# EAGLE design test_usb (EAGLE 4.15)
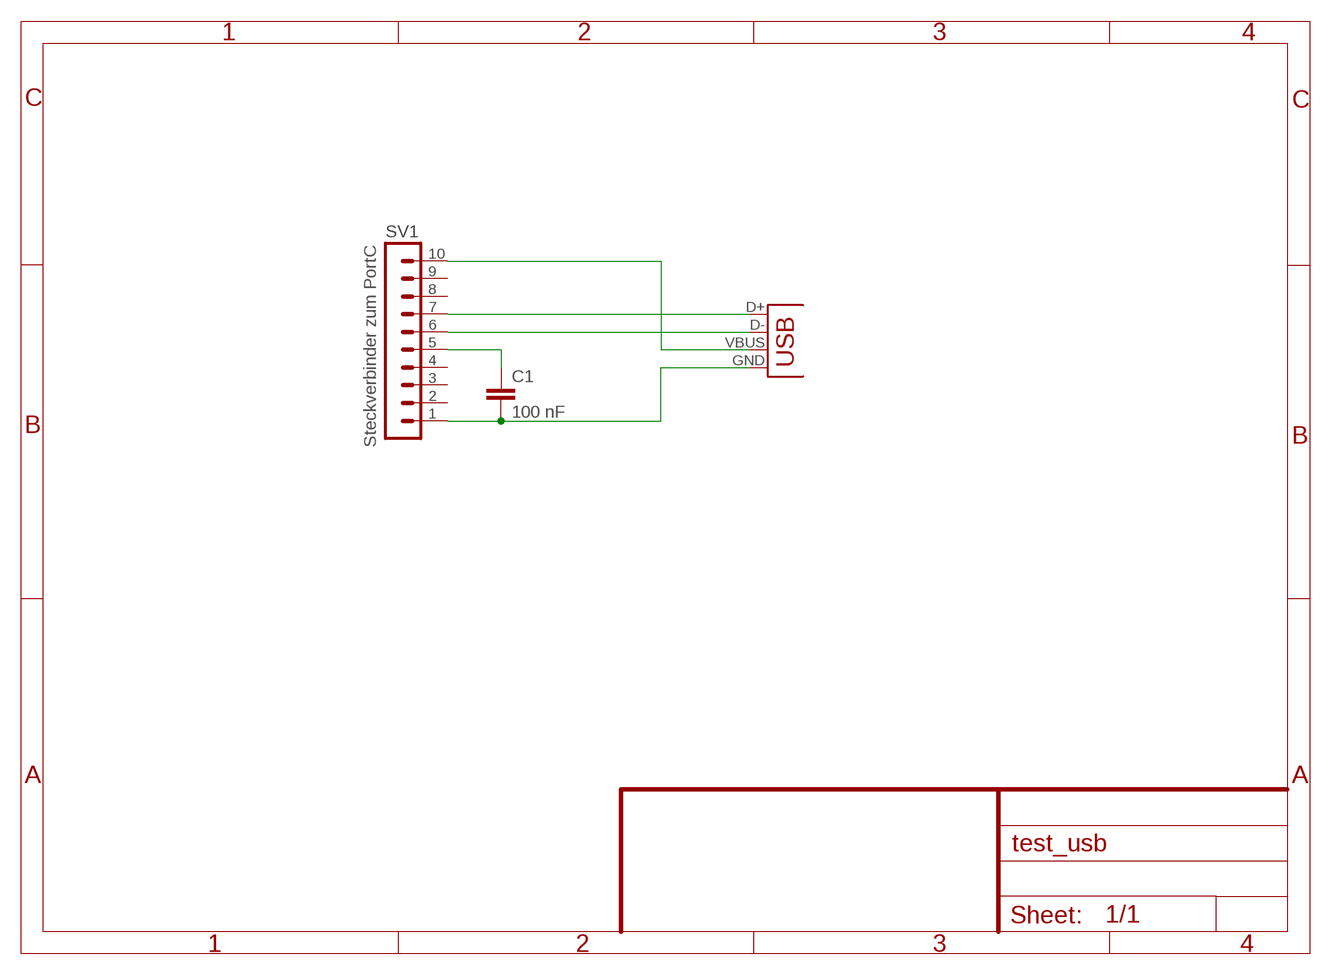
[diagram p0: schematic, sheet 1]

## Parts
C1  100 nF  C-EU025-025X050  [C025-025X050]
SV1  Steckverbinder zum PortC  MA10-1W  [MA10-1W]
X1  USB-B-H  [USB-B-H]

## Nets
N$2: SV1.10 X1.VBUS
N$3: SV1.7 X1.D+
N$4: SV1.6 X1.D-
N$5: C1.1 SV1.5
VSS: C1.2 SV1.1 X1.GND
Unconnected: SV1.2 SV1.3 SV1.4 SV1.8 SV1.9

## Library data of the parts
C1 = rcl:C-EU: CAPACITOR, European symbol
SV1 = con-lstb:MA10-1W: PIN HEADER
X1 = con-usb:USB: USB Connectors

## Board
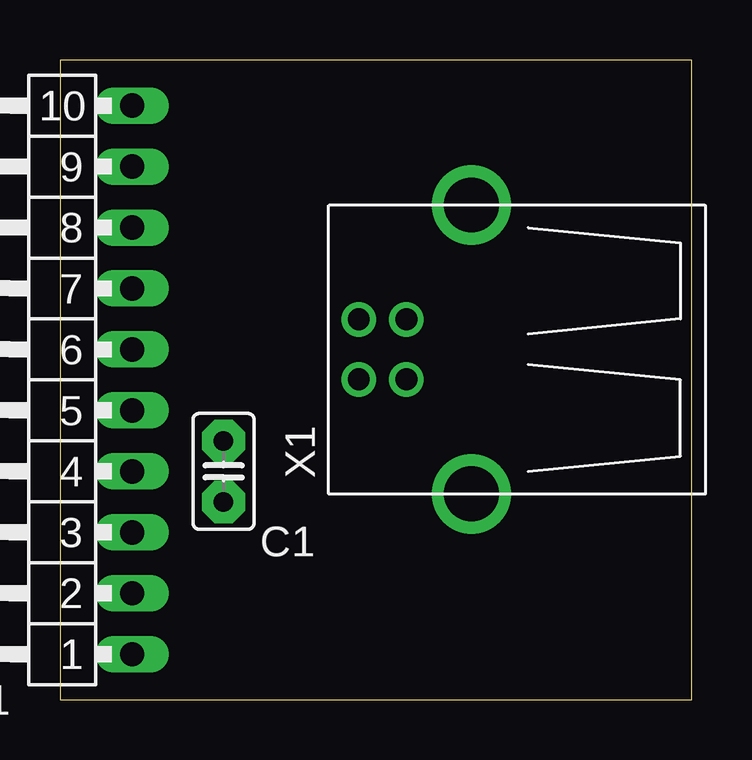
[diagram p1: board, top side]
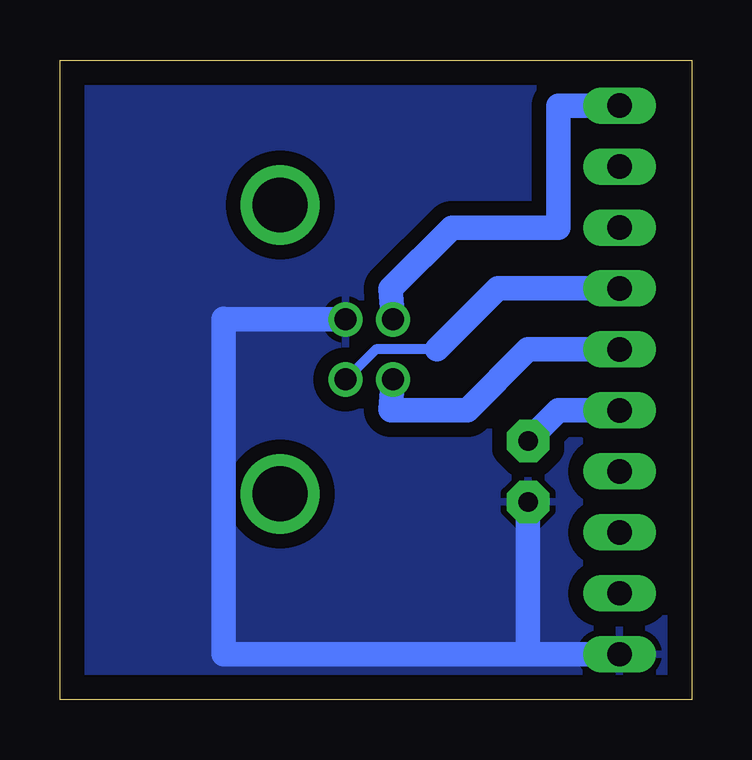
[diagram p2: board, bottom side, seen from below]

Size 26.34 x 26.66 mm. Coordinates in mm from the lower left corner, seen from the top.
Outline: 0,0 26.34,0 26.34,26.66 0,26.66 0,0
Copper layers (1*16): Top 0.035mm / dielectric 1.5mm / Bottom 0.035mm
Design rules "default": minimum track width 10mil, minimum drill 24mil, track to track 8mil, track to pad 8mil, pad to pad 8mil, via to via 8mil, smd to smd 8mil, copper to edge 40mil, drill to drill 8mil, minimum pad ring 10mil, minimum via ring 8mil, stop-mask expansion 4mil, vias tented up to drill 0mil, thermal gap 10mil

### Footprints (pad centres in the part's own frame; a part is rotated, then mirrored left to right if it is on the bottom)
C025-025X050 = drill 0.813 pad 1.778 octagon: 1 -1.27,0; 2 1.27,0
MA10-1W = drill 1.016 long: 1 -11.43,0; 2 -8.89,0; 3 -6.35,0; 4 -3.81,0; 5 -1.27,0; 6 1.27,0; 7 3.81,0; 8 6.35,0; 9 8.89,0; 10 11.43,0
USB-B-H = drill 0.914 round: D+ 0,1.25; D- 1.981,1.25; GND 0,-1.25; VBUS 1.981,-1.25 | drill 2.286 round: SCH1 -2.718,6.02; SCH2 -2.718,-6.02

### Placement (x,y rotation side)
C1  6.82,9.52 270 top
SV1  3.01,13.33 90 top
X1  14.44,14.6 180 top

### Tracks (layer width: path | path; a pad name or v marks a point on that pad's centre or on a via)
N$2
  Bottom 0.406: 12.56,17.12 12.54,17.14
  Bottom 1.016: SV1.10 5.55,24.76 5.55,19.68 10,19.68 12.54,17.14 | X1.VBUS 12.56,17.12
N$3
  Bottom 0.406: 10.63,14.6 13.17,14.6 14.44,13.33 X1.D+
  Bottom 1.016: SV1.7 8.09,17.14 10.63,14.6
N$4
  Bottom 0.406: 12.54,12.06 12.56,12.08
  Bottom 1.016: SV1.6 6.82,14.6 9.36,12.06 12.54,12.06 | 12.56,12.08 X1.D-
N$5
  Bottom 1.016: SV1.5 5.55,12.06 C1.1
VSS
  Bottom 0.406: 19.52,15.87 19.5,15.85
  Bottom 1.016: SV1.1 6.82,1.9 | 6.82,1.9 C1.2 | 19.5,15.85 X1.GND | 19.52,15.87 19.52,1.9 6.82,1.9
  pour Bottom (isolate 0.61): -0.8,27.3 27.14,27.3 27.14,-0.64 -0.8,-0.64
